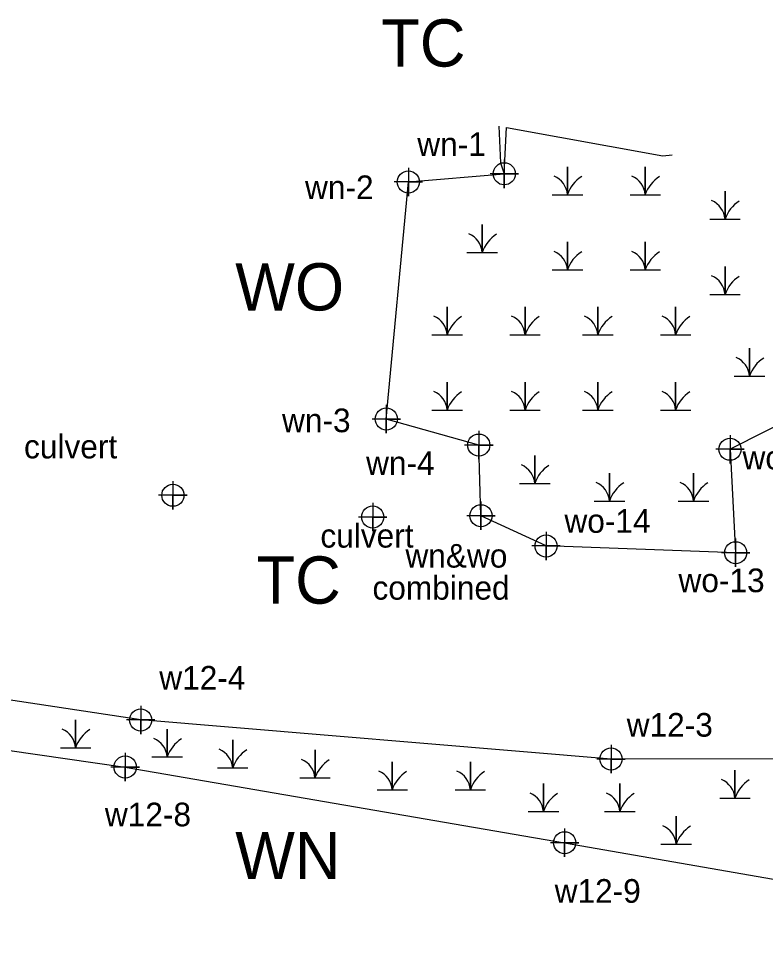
# Model space of a CAD drawing. Extents: x 2174810 to 2196950, y 76168 to 88270.
# Drawn here: x 2192118.1 to 2192275.9, y 86910.8 to 87107.8 of the extents above; entities that cross this region are included whole.
import ezdxf

# ---------------------------------------------------------------- set-up
doc = ezdxf.new("R2010")
doc.units = 0
for name, color, linetype in [('Exist Environmental Wetland Boundary', 7, 'Continuous'), ('Exist Environmental Wetland Boundary Cogo Point CELL', 7, 'Continuous'), ('Exist Environmental Wetland Boundary Text', 7, 'Continuous'), ('Exist Hydro Jurisdictional Stream or Body of Water Mitigable Cogo Number', 7, 'Continuous'), ('Exist Hydro Jurisdictional Stream or Body of Water Mitigable Cogo Point CELL', 7, 'Continuous'), ('Exist Hydro Jurisdictional Stream or Body of Water NonMitigable', 7, 'Continuous'), ('Exist Hydro Jurisdictional Stream or Body of Water NonMitigable Cogo Number', 7, 'Continuous'), ('Exist Hydro Jurisdictional Stream or Body of Water NonMitigable Cogo Point CELL', 7, 'Continuous'), ('Exist Hydro Jurisdictional Stream or Body of Water NonMitigable Text', 7, 'Continuous'), ('Exist Hydro Swamp or Marsh', 7, 'Continuous')]:
    doc.layers.add(name, color=color, linetype=linetype)

msp = doc.modelspace()

# ---------------------------------------------------------------- linework, layer by layer
at = {"layer": 'Exist Environmental Wetland Boundary'}
msp.add_lwpolyline([(2192397.27, 87055.63), (2192394.63, 87019.68), (2192387.28, 86995.48), (2192361.14, 86997.34), (2192334.73, 86992.37), (2192321.6, 87007), (2192314.03, 86992.36), (2192298.56, 86992.36), (2192299.18, 87011.59), (2192290.81, 87028.06), (2192268.47, 87016.75), (2192269.64, 86994.86), (2192229.59, 86996.29), (2192215.81, 87002.68), (2192215.36, 87017.63), (2192195.8, 87023.15), (2192200.47, 87073.29), (2192220.73, 87075.01), (2192221.2, 87084.81), (2192254.26, 87078.79), (2192256.21, 87079.01)], dxfattribs=at)
msp.add_lwpolyline([(2192359.72, 86910.76), (2192412.81, 86942.8), (2192320.42, 86951.32), (2192243.31, 86951.23), (2192143.88, 86959.49), (2192045.01, 86974.5), (2191976.74, 86980.02), (2192028.37, 86965.72), (2192140.6, 86949.53), (2192233.5, 86933.52), (2192319.76, 86918.46)], close=True, dxfattribs=at)
at = {"layer": 'Exist Environmental Wetland Boundary Cogo Point CELL'}
for points in [[(2192220.73, 87078.01), (2192220.73, 87072.01), (2192220.73, 87075.01), (2192223.73, 87075.01), (2192217.73, 87075.01)], [(2192200.47, 87076.29), (2192200.47, 87070.29), (2192200.47, 87073.29), (2192203.47, 87073.29), (2192197.47, 87073.29)], [(2192195.8, 87026.15), (2192195.8, 87020.15), (2192195.8, 87023.15), (2192198.8, 87023.15), (2192192.8, 87023.15)], [(2192215.36, 87020.63), (2192215.36, 87014.63), (2192215.36, 87017.63), (2192218.36, 87017.63), (2192212.36, 87017.63)], [(2192268.47, 87019.75), (2192268.47, 87013.75), (2192268.47, 87016.75), (2192271.47, 87016.75), (2192265.47, 87016.75)], [(2192215.81, 87005.68), (2192215.81, 86999.68), (2192215.81, 87002.68), (2192218.81, 87002.68), (2192212.81, 87002.68)], [(2192229.59, 86999.29), (2192229.59, 86993.29), (2192229.59, 86996.29), (2192232.59, 86996.29), (2192226.59, 86996.29)], [(2192269.64, 86997.86), (2192269.64, 86991.86), (2192269.64, 86994.86), (2192272.64, 86994.86), (2192266.64, 86994.86)], [(2192143.88, 86962.49), (2192143.88, 86956.49), (2192143.88, 86959.49), (2192146.88, 86959.49), (2192140.88, 86959.49)], [(2192140.6, 86952.53), (2192140.6, 86946.53), (2192140.6, 86949.53), (2192143.6, 86949.53), (2192137.6, 86949.53)], [(2192243.31, 86954.23), (2192243.31, 86948.23), (2192243.31, 86951.23), (2192246.31, 86951.23), (2192240.31, 86951.23)], [(2192233.5, 86936.52), (2192233.5, 86930.52), (2192233.5, 86933.52), (2192236.5, 86933.52), (2192230.5, 86933.52)]]:
    msp.add_lwpolyline(points, dxfattribs=at)
for centre in [(2192220.73, 87075.01), (2192200.47, 87073.29), (2192195.8, 87023.15), (2192215.36, 87017.63), (2192268.47, 87016.75), (2192215.81, 87002.68), (2192229.59, 86996.29), (2192269.64, 86994.86), (2192143.88, 86959.49), (2192243.31, 86951.23), (2192140.6, 86949.53), (2192233.5, 86933.52)]:
    msp.add_circle(centre, 2.34, dxfattribs=at)
at = {"layer": 'Exist Hydro Jurisdictional Stream or Body of Water Mitigable Cogo Point CELL'}
msp.add_lwpolyline([(2192192.94, 87005.42), (2192192.94, 86999.42), (2192192.94, 87002.42), (2192195.94, 87002.42), (2192189.94, 87002.42)], dxfattribs=at)
msp.add_circle((2192192.94, 87002.42), 2.34, dxfattribs=at)
at = {"layer": 'Exist Hydro Jurisdictional Stream or Body of Water NonMitigable'}
msp.add_lwpolyline([(2192219.56, 87085.08), (2192219.96, 87077.35), (2192220.73, 87075.01)], dxfattribs=at)
at = {"layer": 'Exist Hydro Jurisdictional Stream or Body of Water NonMitigable Cogo Point CELL'}
msp.add_lwpolyline([(2192150.68, 87010.02), (2192150.68, 87004.02), (2192150.68, 87007.02), (2192153.68, 87007.02), (2192147.68, 87007.02)], dxfattribs=at)
msp.add_circle((2192150.68, 87007.02), 2.34, dxfattribs=at)
at = {"layer": 'Exist Hydro Swamp or Marsh'}
for points in [[(2192230.87, 87070.6), (2192234.1, 87070.6), (2192234.1, 87076.52), (2192234.1, 87070.6), (2192237.32, 87070.6)], [(2192247.32, 87070.6), (2192250.55, 87070.6), (2192250.55, 87076.52), (2192250.55, 87070.6), (2192253.78, 87070.6)], [(2192264.18, 87065.41), (2192267.41, 87065.41), (2192267.41, 87071.33), (2192267.41, 87065.41), (2192270.64, 87065.41)], [(2192212.86, 87058.39), (2192216.09, 87058.39), (2192216.09, 87064.3), (2192216.09, 87058.39), (2192219.31, 87058.39)], [(2192230.87, 87054.68), (2192234.1, 87054.68), (2192234.1, 87060.6), (2192234.1, 87054.68), (2192237.32, 87054.68)], [(2192247.32, 87054.68), (2192250.55, 87054.68), (2192250.55, 87060.6), (2192250.55, 87054.68), (2192253.78, 87054.68)], [(2192264.18, 87049.5), (2192267.41, 87049.5), (2192267.41, 87055.41), (2192267.41, 87049.5), (2192270.64, 87049.5)], [(2192205.46, 87040.97), (2192208.68, 87040.97), (2192208.68, 87046.89), (2192208.68, 87040.97), (2192211.91, 87040.97)], [(2192221.91, 87040.97), (2192225.14, 87040.97), (2192225.14, 87046.89), (2192225.14, 87040.97), (2192228.36, 87040.97)], [(2192237.29, 87040.97), (2192240.51, 87040.97), (2192240.51, 87046.89), (2192240.51, 87040.97), (2192243.74, 87040.97)], [(2192253.74, 87040.97), (2192256.97, 87040.97), (2192256.97, 87046.89), (2192256.97, 87040.97), (2192260.19, 87040.97)], [(2192269.37, 87032.21), (2192272.59, 87032.21), (2192272.59, 87038.13), (2192272.59, 87032.21), (2192275.82, 87032.21)], [(2192205.46, 87025.05), (2192208.68, 87025.05), (2192208.68, 87030.97), (2192208.68, 87025.05), (2192211.91, 87025.05)], [(2192221.91, 87025.05), (2192225.14, 87025.05), (2192225.14, 87030.97), (2192225.14, 87025.05), (2192228.36, 87025.05)], [(2192237.29, 87025.05), (2192240.51, 87025.05), (2192240.51, 87030.97), (2192240.51, 87025.05), (2192243.74, 87025.05)], [(2192253.74, 87025.05), (2192256.97, 87025.05), (2192256.97, 87030.97), (2192256.97, 87025.05), (2192260.19, 87025.05)], [(2192223.96, 87009.5), (2192227.19, 87009.5), (2192227.19, 87015.42), (2192227.19, 87009.5), (2192230.42, 87009.5)], [(2192239.76, 87005.79), (2192242.98, 87005.79), (2192242.98, 87011.71), (2192242.98, 87005.79), (2192246.21, 87005.79)], [(2192257.52, 87005.79), (2192260.75, 87005.79), (2192260.75, 87011.71), (2192260.75, 87005.79), (2192263.97, 87005.79)], [(2192126.9, 86953.62), (2192130.12, 86953.62), (2192130.12, 86959.53), (2192130.12, 86953.62), (2192133.35, 86953.62)], [(2192146.25, 86951.66), (2192149.48, 86951.66), (2192149.48, 86957.58), (2192149.48, 86951.66), (2192152.7, 86951.66)], [(2192160.1, 86949.35), (2192163.33, 86949.35), (2192163.33, 86955.27), (2192163.33, 86949.35), (2192166.55, 86949.35)], [(2192177.5, 86947.22), (2192180.73, 86947.22), (2192180.73, 86953.14), (2192180.73, 86947.22), (2192183.95, 86947.22)], [(2192193.84, 86944.73), (2192197.06, 86944.73), (2192197.06, 86950.65), (2192197.06, 86944.73), (2192200.29, 86944.73)], [(2192210.35, 86944.73), (2192213.58, 86944.73), (2192213.58, 86950.65), (2192213.58, 86944.73), (2192216.8, 86944.73)], [(2192266.28, 86942.96), (2192269.51, 86942.96), (2192269.51, 86948.88), (2192269.51, 86942.96), (2192272.73, 86942.96)], [(2192225.8, 86940.12), (2192229.02, 86940.12), (2192229.02, 86946.03), (2192229.02, 86940.12), (2192232.25, 86940.12)], [(2192241.96, 86940.12), (2192245.18, 86940.12), (2192245.18, 86946.03), (2192245.18, 86940.12), (2192248.41, 86940.12)], [(2192253.85, 86933.19), (2192257.08, 86933.19), (2192257.08, 86939.11), (2192257.08, 86933.19), (2192260.3, 86933.19)]]:
    msp.add_lwpolyline(points, dxfattribs=at)
for centre, radius, start, end in [((2192229.5, 87070.27), 4.61, 4.1403, 67.535), ((2192240.94, 87068.33), 7.21, 122.1274, 161.6222), ((2192245.95, 87070.27), 4.61, 4.1403, 67.535), ((2192257.39, 87068.33), 7.21, 122.1274, 161.6222), ((2192262.81, 87065.08), 4.61, 4.1403, 67.535), ((2192274.25, 87063.14), 7.21, 122.1274, 161.6222), ((2192211.49, 87058.05), 4.61, 4.1403, 67.535), ((2192222.93, 87056.11), 7.21, 122.1274, 161.6222), ((2192229.5, 87054.35), 4.61, 4.1403, 67.535), ((2192240.94, 87052.41), 7.21, 122.1274, 161.6222), ((2192245.95, 87054.35), 4.61, 4.1403, 67.535), ((2192257.39, 87052.41), 7.21, 122.1274, 161.6222), ((2192262.81, 87049.16), 4.61, 4.1403, 67.535), ((2192274.25, 87047.22), 7.21, 122.1274, 161.6222), ((2192204.08, 87040.64), 4.61, 4.1403, 67.535), ((2192215.53, 87038.7), 7.21, 122.1274, 161.6222), ((2192220.54, 87040.64), 4.61, 4.1403, 67.535), ((2192231.98, 87038.7), 7.21, 122.1274, 161.6222), ((2192235.91, 87040.64), 4.61, 4.1403, 67.535), ((2192247.36, 87038.7), 7.21, 122.1274, 161.6222), ((2192252.37, 87040.64), 4.61, 4.1403, 67.535), ((2192263.81, 87038.7), 7.21, 122.1274, 161.6222), ((2192267.99, 87031.88), 4.61, 4.1403, 67.535), ((2192279.43, 87029.94), 7.21, 122.1274, 161.6222), ((2192204.08, 87024.72), 4.61, 4.1403, 67.535), ((2192215.53, 87022.78), 7.21, 122.1274, 161.6222), ((2192220.54, 87024.72), 4.61, 4.1403, 67.535), ((2192231.98, 87022.78), 7.21, 122.1274, 161.6222), ((2192235.91, 87024.72), 4.61, 4.1403, 67.535), ((2192247.36, 87022.78), 7.21, 122.1274, 161.6222), ((2192252.37, 87024.72), 4.61, 4.1403, 67.535), ((2192263.81, 87022.78), 7.21, 122.1274, 161.6222), ((2192222.59, 87009.17), 4.61, 4.1403, 67.535), ((2192234.03, 87007.23), 7.21, 122.1274, 161.6222), ((2192238.38, 87005.46), 4.61, 4.1403, 67.535), ((2192249.82, 87003.52), 7.21, 122.1274, 161.6222), ((2192256.15, 87005.46), 4.61, 4.1403, 67.535), ((2192267.59, 87003.52), 7.21, 122.1274, 161.6222), ((2192125.52, 86953.28), 4.61, 4.1403, 67.535), ((2192136.96, 86951.34), 7.21, 122.1274, 161.6222), ((2192144.88, 86951.33), 4.61, 4.1403, 67.535), ((2192156.32, 86949.39), 7.21, 122.1274, 161.6222), ((2192158.73, 86949.02), 4.61, 4.1403, 67.535), ((2192170.17, 86947.08), 7.21, 122.1274, 161.6222), ((2192176.13, 86946.89), 4.61, 4.1403, 67.535), ((2192187.57, 86944.95), 7.21, 122.1274, 161.6222), ((2192192.46, 86944.4), 4.61, 4.1403, 67.535), ((2192203.9, 86942.46), 7.21, 122.1274, 161.6222), ((2192208.98, 86944.4), 4.61, 4.1403, 67.535), ((2192220.42, 86942.46), 7.21, 122.1274, 161.6222), ((2192264.91, 86942.62), 4.61, 4.1403, 67.535), ((2192276.35, 86940.69), 7.21, 122.1274, 161.6222), ((2192224.42, 86939.78), 4.61, 4.1403, 67.535), ((2192235.86, 86937.84), 7.21, 122.1274, 161.6222), ((2192240.58, 86939.78), 4.61, 4.1403, 67.535), ((2192252.02, 86937.84), 7.21, 122.1274, 161.6222), ((2192252.48, 86932.85), 4.61, 4.1403, 67.535), ((2192263.92, 86930.92), 7.21, 122.1274, 161.6222)]:
    msp.add_arc(centre, radius, start, end, dxfattribs=at)

# ---------------------------------------------------------------- texts
at = {"layer": 'Exist Environmental Wetland Boundary Text'}
for s, p in [('WO', (2192163.86, 87046.1)), ('WN', (2192163.86, 86925.82))]:
    msp.add_text(s, height=10, dxfattribs=at).set_placement(p)
at = {"layer": 'Exist Hydro Jurisdictional Stream or Body of Water Mitigable Cogo Number'}
for s, p in [('wn-1', (2192202.35, 87078.77)), ('wn-2', (2192178.62, 87069.66)), ('wn-3', (2192173.76, 87020.36)), ('wo-12', (2192271.11, 87012.48)), ('wn-4', (2192191.53, 87011.33)), ('wo-14', (2192233.46, 86999.08)), ('wn&wo', (2192199.85, 86991.72)), ('combined', (2192192.88, 86984.94)), ('wo-13', (2192257.57, 86986.52)), ('w12-4', (2192147.81, 86965.91)), ('w12-3', (2192246.62, 86955.96)), ('w12-8', (2192136.31, 86937)), ('w12-9', (2192231.39, 86920.83))]:
    msp.add_text(s, height=5, dxfattribs=at).set_placement(p)
at = {"layer": 'Exist Hydro Jurisdictional Stream or Body of Water NonMitigable Cogo Number'}
for p in [(2192119.22, 87014.82), (2192181.87, 86995.95)]:
    msp.add_text('culvert', height=5, dxfattribs=at).set_placement(p)
at = {"layer": 'Exist Hydro Jurisdictional Stream or Body of Water NonMitigable Text'}
for p in [(2192194.72, 87097.69), (2192168.36, 86984.09)]:
    msp.add_text('TC', height=10, dxfattribs=at).set_placement(p)

doc.saveas('drawing.dxf')
